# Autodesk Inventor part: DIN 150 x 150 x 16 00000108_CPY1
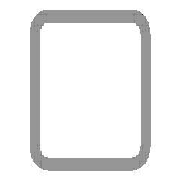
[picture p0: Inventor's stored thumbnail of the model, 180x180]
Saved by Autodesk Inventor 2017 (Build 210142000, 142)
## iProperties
Created: 2017-11
Part Number: DIN 150 x 150 x 16 00000108_CPY1
Material: Steel, Mild
Description: Cold formed welded structural hollow sections of non-alloy and fine grain structural steel
Document SubType Name: Modeling
Standard: DIN
Designer: iusti
Standard Revision: 2006-07
Standards Organization: DIN
Language: en-US
Size Designation: 150 x 150 x 16
Categories: <MemberInstance><Categories><Category DisplayName="Structural Shapes" InternalName="089c4875-fa83-4c05-b084-43b9cc11f5ed" Mnemonic="GRDR"><CategoryParameter Dis
Stock Number: 150 x 150 x 16
Mass: 58696.3 g
Surface Area: 9558.04 cm^2
Volume: 7477.24 cm^3
Density: 7.85 g/cm^3
Appearance: Semi-Polished
IsCustomPart: 1
G_W: 150.000 mm
G_H: 150.000 mm
G_L: 1150.000 mm
+D0655DDE-97F9-4B99-A490-E36C02108510+CUTDETAIL1: Miter 45.00 deg
+B95BDB02-C4C2-4ECB-9363-19BA39C44CCB+CUTDETAIL2: Miter 45.00 deg
_CCFamilyMember: 76
_CCFamilyDisplayName: DIN EN 10219-2 (Square Hollow Section - Cold Formed) - Cold formed welded structural hollow sections of non-alloy and fine grain structural steel
_FrameMemberDoc: Frame Member File
_Version: 15.0.0
_GetPNFromCC: 1
Author: iusti
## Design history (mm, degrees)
node "Start plane"
node "End plane"
sketch "Sketch"
  geometry: L1 (-75, -27)-(-75, 27); L2 (-27, 75)-(27, 75); L3 (75, 27)-(75, -27); L4 (27, -75)-(-27, -75); L5 (-27, 59)-(27, 59); L6 (59, 27)-(59, -27); L7 (27, -59)-(-27, -59); L8 (-59, -27)-(-59, 27); L9 (0, 118.918)-(0, -118.918) reference; L10 (-118.918, 0)-(118.918, 0) reference; A1 r 48 centre (-27, -27) between (-75, -27) and (-27, -75); A2 r 48 centre (-27, 27) between (-27, 75) and (-75, 27); A3 r 48 centre (27, 27) between (75, 27) and (27, 75); A4 r 48 centre (27, -27) between (27, -75) and (75, -27); A5 r 32 centre (-27, 27) between (-27, 59) and (-59, 27); A6 r 32 centre (27, 27) between (59, 27) and (27, 59); A7 r 32 centre (27, -27) between (27, -59) and (59, -27); A8 r 32 centre (-27, -27) between (-59, -27) and (-27, -59)
  constraints: 16 end point, 16 point on circle, 8 centre point, 8 tangent, 4 parallel, 3 equal radius, 2 perpendicular, 7 other
  dimensions: "d7" = 48 radius of A1 (= G_IR); "d10" = 150 distance between parallel lines of L2 L4 (= G_H); "d11" = 150 distance between parallel lines of L1 L3 (= G_W); "d12" = 16 distance between parallel lines of L3 L6 (= G_T); "d15" = 75 distance between parallel lines of L2 L10 (= 0.5 x d10); "d16" = 75 distance between parallel lines of L9 L3 (= 0.5 x d11)
extrude "Body" new body sketch "Sketch" stored distance "d3" = 1150 (= G_L); taper "d4" = 0 deg
node "Driven Length"
  sketch "Sketch3"
    geometry: L1 (0, 0)-(10, 0) reference
    constraints: 2 end point, 1 horizontal
  workplane "Work Plane3"
  sketch "Sketch4"
    geometry: L1 (-2, -75)-(12, -75) reference; L2 (-2, 1075)-(12, 1075) reference
    dimensions: "d18" = 1150 distance between parallel lines of L1 L2 (derived)
workplane "Work Plane4"
split "Split1"
workplane "Work Plane5"
split "Split2"
body "Solid1"
other parameters: "G_W" = 150 [user parameter; used in 1 equation term], "G_H" = 150 [user parameter; used in 1 equation term], "G_T" = 16 [user parameter; used in 1 equation term], "G_IR" = 48 [user parameter; used in 1 equation term], "G_L" = 1150 (= d18) [user parameter; used in 1 equation term], "G_OFFSET_START" = 75 [user parameter; used in 1 equation term], "G_OFFSET_END" = 75 [user parameter; used in 1 equation term], "d13" = -75 (= -G_OFFSET_START), "d14" = 1075 (= G_OFFSET_END + B_L), "d17" = 90 deg
